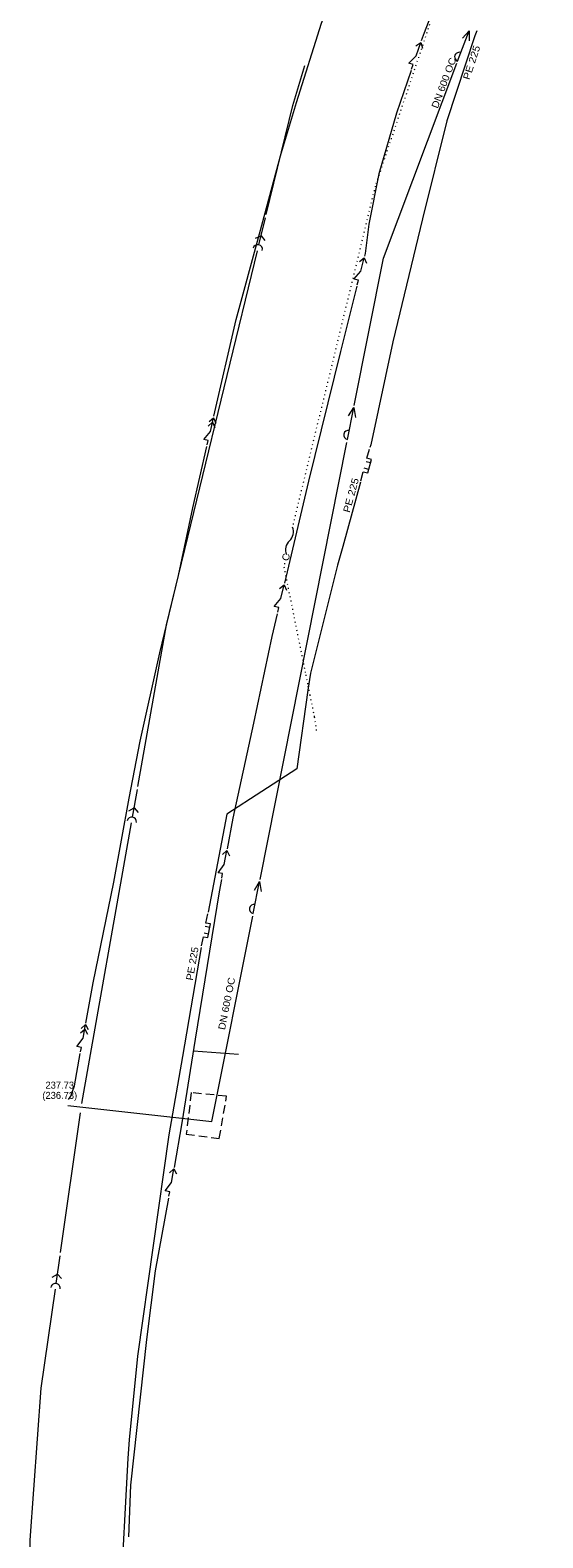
# Model space of a CAD drawing. Extents: x -601552 to -601367, y -1161450 to -1160710.
# Drawn here: x -601551.3 to -601496.3, y -1161083.9 to -1160922.2 of the extents above; entities that cross this region are included whole.
import ezdxf
from ezdxf.enums import TextEntityAlignment as Align

# ---------------------------------------------------------------- set-up
doc = ezdxf.new("R2010")
doc.units = 0
doc.header["$LTSCALE"] = 0.3
doc.linetypes.add('DOTTED', pattern=[1.5, 0.3, -1.2])
doc.linetypes.add('MEDIUM_DASHED', pattern=[4.5, 3, -1.5])
for name, color, linetype, lineweight in [('34', 7, 'Continuous', 13), ('41', 7, 'Continuous', 13), ('54', 7, 'Continuous', 13), ('56', 7, 'Continuous', 13), ('57', 7, 'Continuous', 13), ('59', 7, 'Continuous', 13)]:
    doc.layers.add(name, color=color, linetype=linetype, lineweight=lineweight)

msp = doc.modelspace()

# ---------------------------------------------------------------- linework, layer by layer
at = {"layer": '34', "linetype": 'DOTTED'}
for points in [[(-601508.46, -1160921.59), (-601514.29, -1160938.92), (-601523.126, -1160975.284)], [(-601524.007, -1160979.383), (-601524.09, -1160979.78), (-601521.91, -1160990.57), (-601521.75, -1160991.36), (-601521.51, -1160992.53), (-601521.31, -1160993.52), (-601520.83, -1160995.86), (-601520.562, -1160997.656)]]:
    msp.add_lwpolyline(points, dxfattribs=at)
at = {"layer": '34'}
for centre, start, end in [((-601524.3165, -1160976.0369), 311.00336, 24.74315), ((-601522.6763, -1160977.9236), 131.00336, 204.74315)]:
    msp.add_arc(centre, 1.25, start, end, dxfattribs=at)
at = {"layer": '41'}
for p, q in [((-601526.778, -1160945.229), (-601526.07, -1160942.313)), ((-601540.324, -1161006.619), (-601539.803, -1161003.665)), ((-601545.753, -1161037.358), (-601540.433, -1161007.233)), ((-601548.05, -1161053.331), (-601545.913, -1161038.345)), ((-601548.524, -1161056.655), (-601548.101, -1161053.685))]:
    msp.add_line(p, q, dxfattribs=at)
for points in [[(-601525.984, -1160941.96), (-601523.144, -1160930.272), (-601521.836, -1160925.977)], [(-601527.122, -1160944.528), (-601526.542, -1160944.257), (-601526.15, -1160944.764)], [(-601539.747, -1161003.353), (-601536.681, -1160985.99), (-601526.934, -1160945.872)], [(-601540.712, -1161005.941), (-601540.15, -1161005.634), (-601539.728, -1161006.115)], [(-601548.934, -1161055.991), (-601548.383, -1161055.665), (-601547.944, -1161056.132)], [(-601551.255, -1161092.771), (-601551.31, -1161084.207), (-601550.128, -1161067.903), (-601548.609, -1161057.251)]]:
    msp.add_lwpolyline(points, dxfattribs=at)
for centre, start, end in [((-601526.8958, -1160945.7145), 346.34425, 166.34425), ((-601540.4112, -1161007.1115), 349.98441, 169.98441), ((-601548.5947, -1161057.1502), 351.88462, 171.88462)]:
    msp.add_arc(centre, 0.5, start, end, dxfattribs=at)
at = {"layer": '54'}
for p, q in [((-601514.988, -1160969.328), (-601515.47, -1160969.196)), ((-601514.798, -1160968.632), (-601515.28, -1160968.5)), ((-601532.164, -1161019.175), (-601532.655, -1161019.081)), ((-601532.028, -1161018.466), (-601532.52, -1161018.372))]:
    msp.add_line(p, q, dxfattribs=at)
for points in [[(-601503.395, -1160922.267), (-601503.62, -1160922.8), (-601506.61, -1160931.92), (-601509.22, -1160942.44), (-601512.41, -1160955.65), (-601514.78, -1160966.67), (-601514.866, -1160966.986)], [(-601515.835, -1160970.533), (-601515.572, -1160969.568), (-601515.089, -1160969.7), (-601514.694, -1160968.253), (-601515.176, -1160968.121), (-601514.913, -1160967.157)], [(-601515.874, -1160970.676), (-601517.76, -1160977.58), (-601518.34, -1160979.61), (-601521.22, -1160991.19), (-601521.51, -1160992.99), (-601522.69, -1161001.45), (-601530.2, -1161006.3), (-601532.222, -1161016.817)], [(-601532.916, -1161020.442), (-601532.728, -1161019.46), (-601532.237, -1161019.554), (-601531.955, -1161018.08), (-601532.446, -1161017.986), (-601532.258, -1161017.004)], [(-601532.951, -1161020.626), (-601534.98, -1161032.29), (-601536.45, -1161040.7), (-601539.81, -1161064.45), (-601540.69, -1161073.43), (-601540.83, -1161075.41), (-601541.64, -1161090.76), (-601541.79, -1161115.65), (-601541.6, -1161120.34), (-601541.506, -1161122.464)]]:
    msp.add_lwpolyline(points, dxfattribs=at)
at = {"layer": '56'}
for p, q in [((-601505.45, -1160925.538), (-601504.217, -1160922.263)), ((-601517.268, -1160966.113), (-601516.586, -1160962.68)), ((-601526.647, -1161013.31), (-601517.328, -1160966.415)), ((-601527.376, -1161016.976), (-601526.693, -1161013.543))]:
    msp.add_line(p, q, dxfattribs=at)
for points in [[(-601504.92, -1160923.066), (-601504.217, -1160922.263), (-601504.218, -1160923.331)], [(-601516.542, -1160962.458), (-601513.4, -1160946.65), (-601505.527, -1160925.742)], [(-601517.148, -1160963.588), (-601516.586, -1160962.68), (-601516.413, -1160963.734)], [(-601527.256, -1161014.451), (-601526.693, -1161013.543), (-601526.521, -1161014.597)], [(-601547.277, -1161037.568), (-601531.81, -1161039.29), (-601527.433, -1161017.265)]]:
    msp.add_lwpolyline(points, dxfattribs=at)
at = {"layer": '56', "linetype": 'MEDIUM_DASHED'}
msp.add_lwpolyline([(-601534.027, -1161036.18), (-601534.569, -1161040.638), (-601531.018, -1161041.09), (-601530.236, -1161036.575)], close=True, dxfattribs=at)
at = {"layer": '56'}
for centre, start, end in [((-601505.2742, -1160925.0703), 69.36618, 249.36618), ((-601517.1703, -1160965.6223), 78.76026, 258.76026), ((-601527.2782, -1161016.4857), 78.76026, 258.76026)]:
    msp.add_arc(centre, 0.5, start, end, dxfattribs=at)
at = {"layer": '57'}
msp.add_line((-601533.774, -1161031.694), (-601528.944, -1161032.051), dxfattribs=at)
for points in [[(-601496.31, -1160900.88), (-601496.522, -1160900.861), (-601498.58, -1160899.917), (-601498.884, -1160899.898), (-601499.089, -1160900.135), (-601500.29, -1160902.699), (-601503.007, -1160907.893), (-601506.126, -1160914.909), (-601509.046, -1160922.474), (-601509.347, -1160923.345)], [(-601510.389, -1160926.364), (-601510.226, -1160925.892), (-601510.699, -1160925.728), (-601509.9, -1160924.946), (-601509.41, -1160923.528)], [(-601509.928, -1160923.879), (-601509.41, -1160923.528), (-601509.219, -1160924.123)], [(-601510.449, -1160926.537), (-601512.024, -1160931.099), (-601513.907, -1160937.618), (-601514.972, -1160943), (-601515.368, -1160946.173), (-601515.439, -1160946.453)], [(-601516.215, -1160949.513), (-601516.092, -1160949.029), (-601516.577, -1160948.906), (-601515.846, -1160948.059), (-601515.478, -1160946.605)], [(-601515.964, -1160946.998), (-601515.478, -1160946.605), (-601515.237, -1160947.182)], [(-601516.254, -1160949.666), (-601518.027, -1160956.658), (-601521.456, -1160970.587), (-601524.028, -1160981.531)], [(-601524.754, -1160984.621), (-601524.64, -1160984.134), (-601525.126, -1160984.02), (-601524.411, -1160983.161), (-601524.068, -1160981.701)], [(-601524.547, -1160982.102), (-601524.068, -1160981.701), (-601523.817, -1160982.273)], [(-601524.796, -1160984.798), (-601525.37, -1160987.242), (-601527.352, -1160996.534), (-601529.573, -1161006.718), (-601530.178, -1161010.025)], [(-601530.755, -1161013.172), (-601530.665, -1161012.68), (-601531.157, -1161012.59), (-601530.485, -1161011.697), (-601530.214, -1161010.221)], [(-601530.673, -1161010.645), (-601530.214, -1161010.221), (-601529.936, -1161010.781)], [(-601530.783, -1161013.327), (-601531.022, -1161014.631), (-601533.622, -1161030.444), (-601535.03, -1161039.41), (-601535.874, -1161044.203)], [(-601536.421, -1161047.306), (-601536.334, -1161046.814), (-601536.826, -1161046.727), (-601536.161, -1161045.829), (-601535.9, -1161044.352)], [(-601536.356, -1161044.779), (-601535.9, -1161044.352), (-601535.618, -1161044.909)], [(-601536.457, -1161047.491), (-601537.884, -1161055.317), (-601538.846, -1161062.656), (-601540.549, -1161078.28), (-601540.766, -1161083.834)]]:
    msp.add_lwpolyline(points, dxfattribs=at)
at = {"layer": '59'}
for points in [[(-601531.601, -1160963.611), (-601529.22, -1160953.226), (-601526.689, -1160944.051), (-601524.454, -1160935.681), (-601522.748, -1160929.969), (-601520.049, -1160921.46), (-601518.324, -1160917.13)], [(-601532.307, -1160966.698), (-601532.196, -1160966.211), (-601532.683, -1160966.099), (-601531.973, -1160965.236), (-601531.638, -1160963.774)], [(-601532.227, -1160964.665), (-601531.75, -1160964.261), (-601531.496, -1160964.832)], [(-601532.115, -1160964.178), (-601531.638, -1160963.774), (-601531.384, -1160964.345)], [(-601545.338, -1161028.725), (-601544.543, -1161024.385), (-601542.327, -1161013.615), (-601540.691, -1161004.597), (-601539.498, -1160998.492), (-601537.387, -1160988.993), (-601535.396, -1160980.692), (-601533.849, -1160973.432), (-601532.342, -1160966.848)], [(-601545.904, -1161031.814), (-601545.814, -1161031.322), (-601546.306, -1161031.232), (-601545.633, -1161030.338), (-601545.363, -1161028.863)], [(-601545.912, -1161029.779), (-601545.453, -1161029.355), (-601545.175, -1161029.914)], [(-601545.822, -1161029.287), (-601545.363, -1161028.863), (-601545.084, -1161029.422)], [(-601547.183, -1161036.917), (-601546.953, -1161036.563), (-601546.568, -1161035.439), (-601545.934, -1161031.979)]]:
    msp.add_lwpolyline(points, dxfattribs=at)

# ---------------------------------------------------------------- texts
at = {"layer": '34', "width": 1.1}
msp.add_text('C', height=0.75, rotation=77.873, dxfattribs=at).set_placement((-601523.4218, -1160978.4166), align=Align.RIGHT)
at = {"layer": '41'}
for s, p in [('(236.73)', (-601548.135, -1161036.85)), ('237.73', (-601548.135, -1161035.751))]:
    msp.add_text(s, height=0.75, dxfattribs=at).set_placement(p, align=Align.CENTER)
at = {"layer": '54'}
for rotation, width, p in [(71.848, 1.15, (-601503.009, -1160923.9887)), (74.723, 1.15, (-601516.0349, -1160970.3626)), (80.13, 1.1, (-601533.2371, -1161020.6256))]:
    msp.add_text('PE 225', height=0.75, rotation=rotation, dxfattribs=dict(at, width=width)).set_placement(p, align=Align.RIGHT)
at = {"layer": '56', "width": 1.1}
for rotation, p in [(69.366, (-601505.5782, -1160925.3163)), (78.76, (-601529.3048, -1161023.9052))]:
    msp.add_text('DN 600 OC', height=0.75, rotation=rotation, dxfattribs=at).set_placement(p, align=Align.RIGHT)

doc.saveas('drawing.dxf')
